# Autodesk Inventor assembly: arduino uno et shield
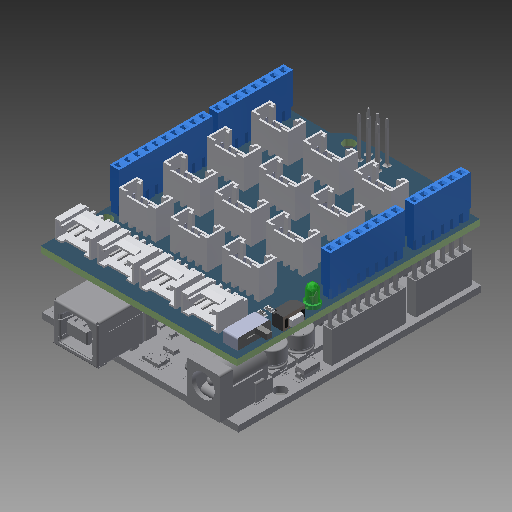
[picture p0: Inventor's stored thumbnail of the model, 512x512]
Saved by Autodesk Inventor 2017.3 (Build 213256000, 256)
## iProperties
Part Number: arduino uno et shield
Material: Générique
Document SubType Name: Assembly
Designer: ficho
Author: ficho
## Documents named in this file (3)
- G:\travail\année 2019-2020\réforme\avant février\IT\arduino uno et shield.iam
- G:\travail\année 2019-2020\réforme\avant février\IT\Grove shield Uno.ipt
- G:\travail\année 2019-2020\réforme\avant février\IT\arduino uno.ipt
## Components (2 placed, 2 different names)
1. Grove shield Uno:1 — Placage:1
2. arduino uno:1 — Placage:1
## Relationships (1: Mate 1)
- Placage:1 [Mate]: Grove shield Uno:1 ↔ arduino uno:1
